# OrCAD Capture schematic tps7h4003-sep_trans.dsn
size Custom; title: TPS7H4003-SEP Radiation-Tolerant 3-V to 7-V Input; rev: *; note: Datasheet: SLVSG41    EVM User Guide: SLVUC73; note: 18-A Synchronous Buck Converter in Space Enhanced Plastic
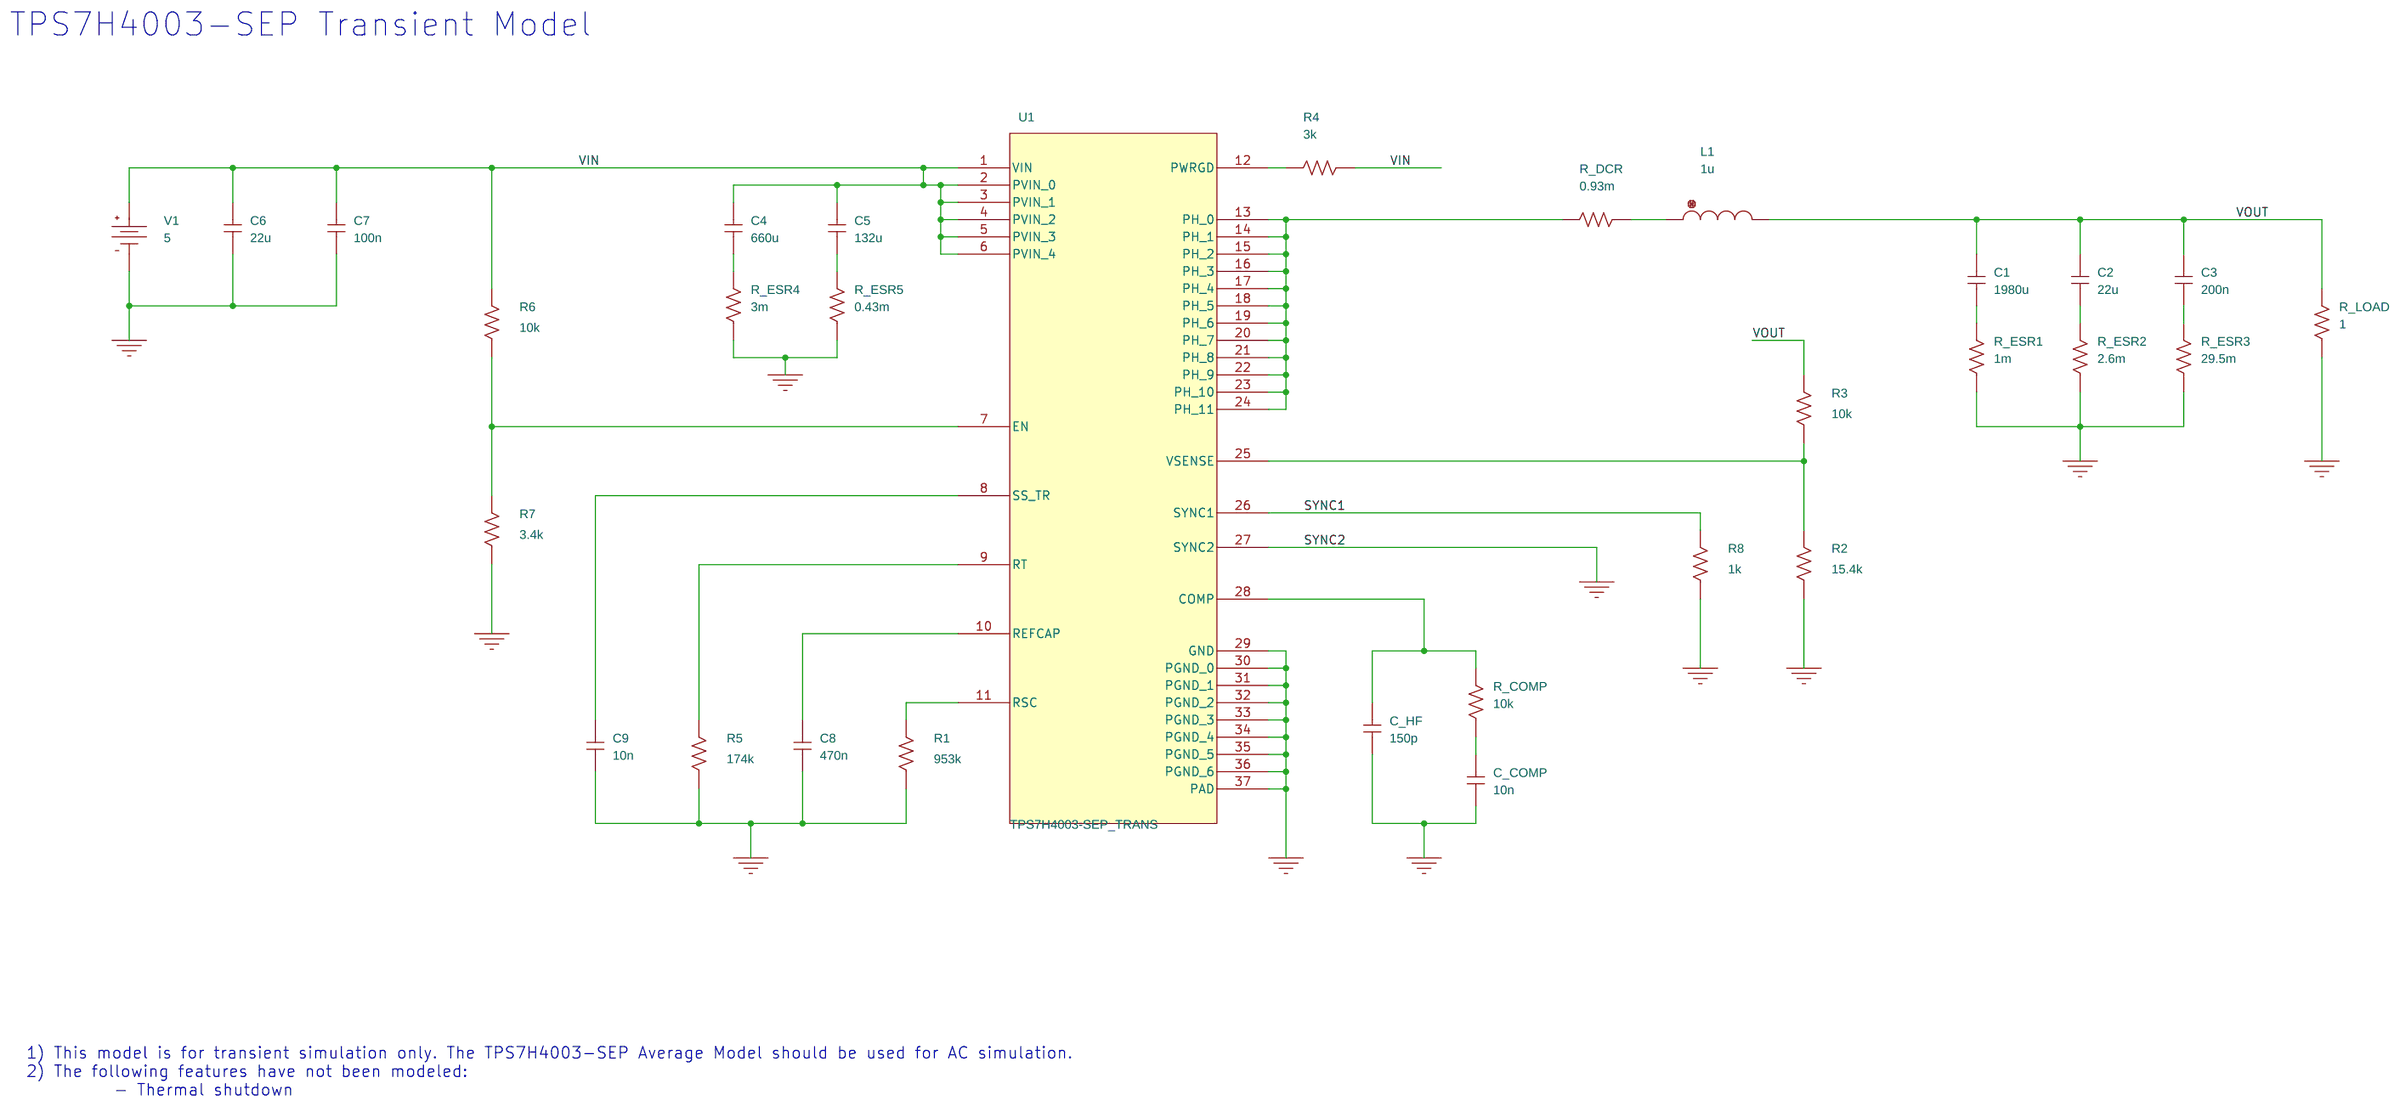
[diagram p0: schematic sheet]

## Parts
C1  1980u  [cap196]
C2  22u  [cap196]
C3  200n  [cap196]
C4  660u  [cap196]
C5  132u  [cap196]
C6  22u  [cap196]
C7  100n  [cap196]
C8  470n  [cap196]
C9  10n  [cap196]
C_COMP  10n  [cap196]
C_HF  150p  [cap196]
L1  1u  [DISC350x175LS200x100034]
R1  953k  [AXRC05]
R2  15.4k  [AXRC05]
R3  10k  [AXRC05]
R4  3k  [AXRC05]
R5  174k  [AXRC05]
R6  10k  [AXRC05]
R7  3.4k  [AXRC05]
R8  1k  [AXRC05]
R_COMP  10k  [AXRC05]
R_DCR  0.93m  [AXRC05]
R_ESR1  1m  [AXRC05]
R_ESR2  2.6m  [AXRC05]
R_ESR3  29.5m  [AXRC05]
R_ESR4  3m  [AXRC05]
R_ESR5  0.43m  [AXRC05]
R_LOAD  1  [AXRC05]
U1  TPS7H4003-SEP_TRANS
V1  VDC

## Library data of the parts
C1-C9 C_COMP C_HF = C
L1 = L
R1-R8 R_COMP R_DCR R_ESR1-R_ESR5 R_LOAD = R
U1 = TPS7H4003-SEP_TRANS_3: PSpiceTemplate: X^@REFDES  %VIN %PVIN_0 %PVIN_1 %PVIN_2 %PVIN_3 %PVIN_4 %EN %SS_TR %RT %REFCAP %RSC %PWRGD %PH_0 %PH_1 %PH_2 %PH_3 %PH_4 %PH_5 %PH_6 %PH_7 %PH_8 %PH_9 %PH_10 %PH_11 %VSENSE %SYNC1 %SYNC2 %COMP %GND %PGND_0 %PGND_1 %PGND_2 %PGND_3 %PGND_4 %PGND_5 %PGND_6 %PAD @MODEL
V1 = VDC: DC: 5

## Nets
VIN: C4.2 C5.2 C6.2 C7.2 R4.1 R6.2 U1.1(VIN) U1.2(PVIN_0) U1.3(PVIN_1) U1.4(PVIN_2) U1.5(PVIN_3) U1.6(PVIN_4) V1.0(+)
0: C6.1 C7.1 C8.1 C9.1 C_COMP.1 C_HF.1 R1.1 R2.1 R5.1 R7.1 R8.1 R_ESR1.1 R_ESR2.1 R_ESR3.1 R_ESR4.1 R_ESR5.1 R_LOAD.1 U1.27(SYNC2) U1.29(GND) U1.30(PGND_0) U1.31(PGND_1) U1.32(PGND_2) U1.33(PGND_3) U1.34(PGND_4) U1.35(PGND_5) U1.36(PGND_6) U1.37(PAD) V1.1(-)
SYNC1: R8.2 U1.26(SYNC1)
VOUT: C1.2 C2.2 C3.2 L1.2 R3.2 R_LOAD.2
N16775106: R_DCR.2 U1.13(PH_0) U1.14(PH_1) U1.15(PH_2) U1.16(PH_3) U1.17(PH_4) U1.18(PH_5) U1.19(PH_6) U1.20(PH_7) U1.21(PH_8) U1.22(PH_9) U1.23(PH_10) U1.24(PH_11)
N16775118: L1.1 R_DCR.1
N16775296: C1.1 R_ESR1.2
N16775300: C2.1 R_ESR2.2
N16775304: C3.1 R_ESR3.2
N16775482: R2.2 R3.1 U1.25(VSENSE)
N16775506: C_HF.2 R_COMP.2 U1.28(COMP)
N16775614: C_COMP.2 R_COMP.1
N16775618: R1.2 U1.11(RSC)
N16779303: R4.2 U1.12(PWRGD)
N16779515: C8.2 U1.10(REFCAP)
N16779536: R5.2 U1.9(RT)
N16779554: C9.2 U1.8(SS_TR)
N16779995: R6.1 R7.2 U1.7(EN)
N16783538: C4.1 R_ESR4.2
N16783540: C5.1 R_ESR5.2

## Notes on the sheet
- TPS7H4003-SEP Transient Model
- 1) This model is for transient simulation only. The TPS7H4003-SEP Average Model should be used for AC simulation.
  2) The following features have not been modeled:
            - Thermal shutdown
